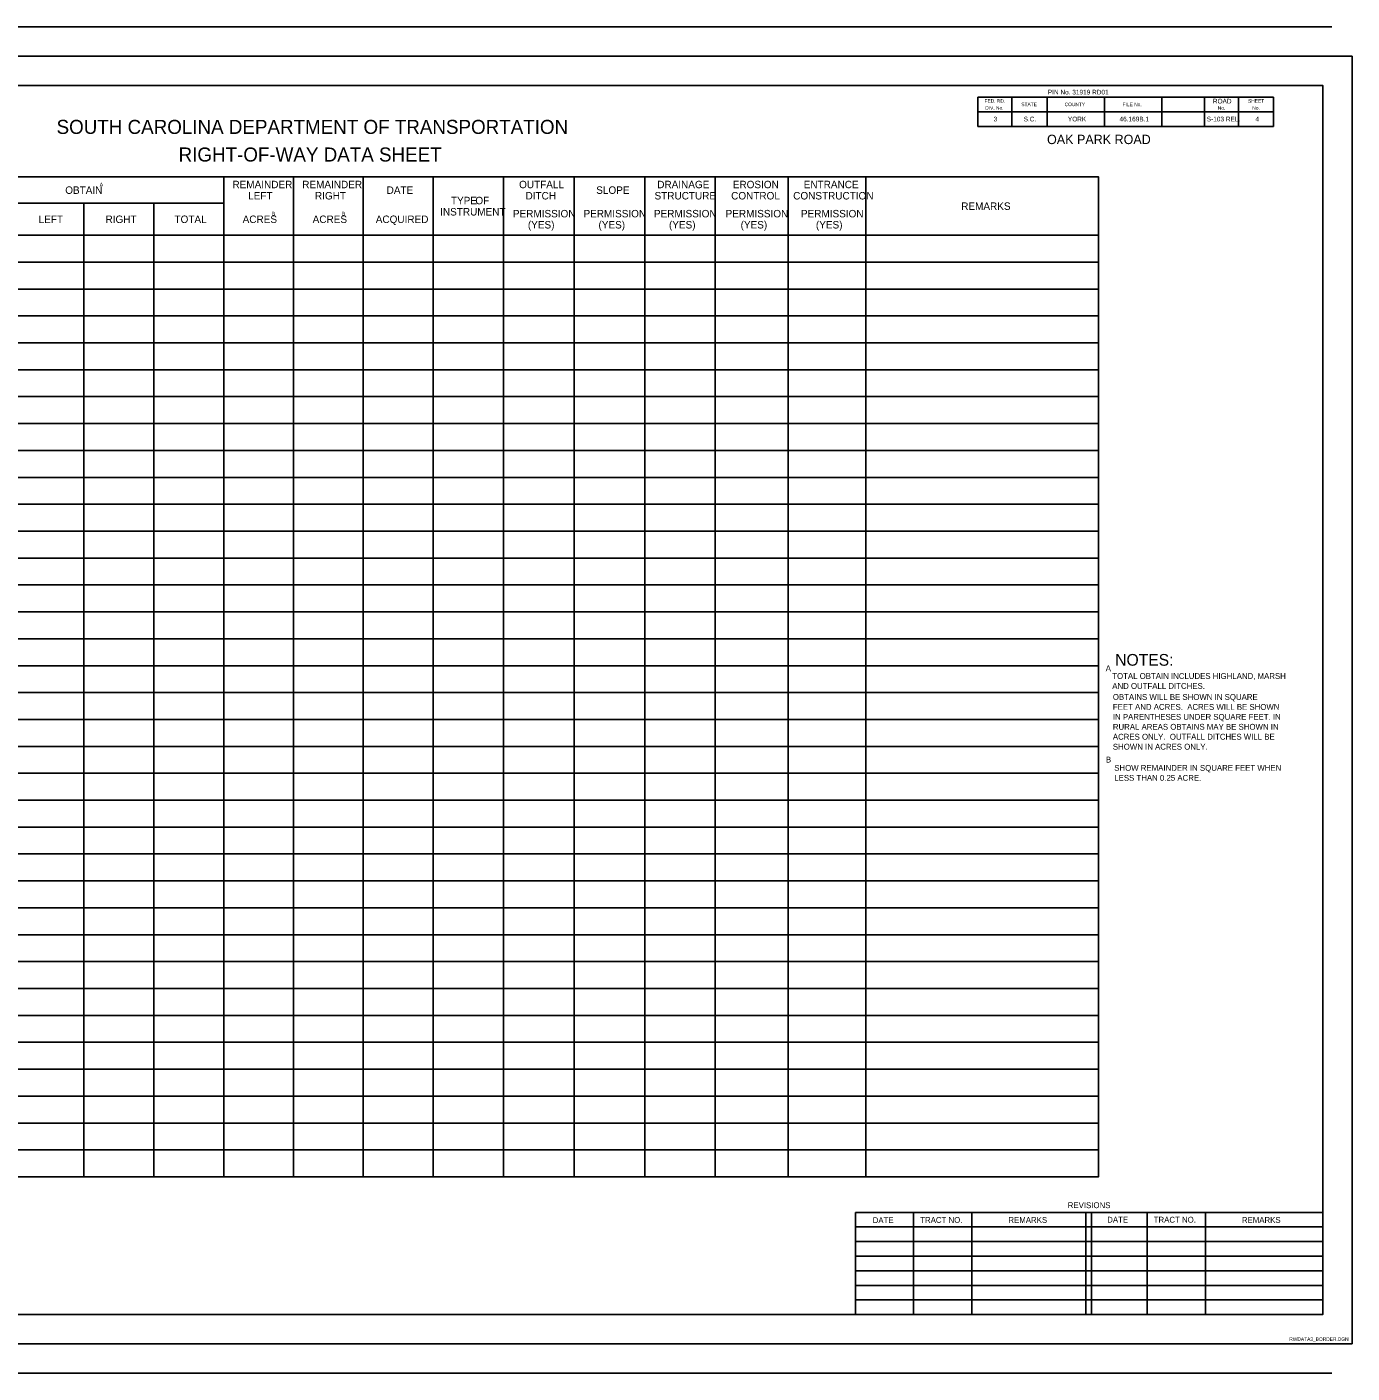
# Model space of a CAD drawing. Extents: x -19 to 1777, y -25 to 1125.
# Drawn here: x 646 to 1777, y -25 to 1125 of the extents above; entities that cross this region are included whole.
import ezdxf

# ---------------------------------------------------------------- set-up
doc = ezdxf.new("R2010")
doc.units = 0
for name, color, linetype in [('RD_SHT_Bndy', 7, 'Continuous'), ('RD_SHT_Iplotshp', 7, 'Continuous'), ('RD_SHT_MjGrid', 7, 'Continuous'), ('RD_SHT_TX', 7, 'Continuous'), ('RD_TX_RW', 7, 'Continuous')]:
    doc.layers.add(name, color=color, linetype=linetype)

msp = doc.modelspace()

# ---------------------------------------------------------------- linework, layer by layer
at = {"layer": 'RD_SHT_Bndy'}
for p, q in [((0, 1125), (1760, 1125)), ((0, 1100), (1760, 1100)), ((1457.9, 1065), (1710.4, 1065)), ((1457.9, 1065), (1457.9, 1052.5)), ((1486.9, 1065), (1486.9, 1052.5)), ((1516.9, 1065), (1516.9, 1052.5)), ((1565.9, 1065), (1565.9, 1052.5)), ((1614.9, 1065), (1614.9, 1052.5)), ((1651.4, 1065), (1651.4, 1052.5)), ((1680.4, 1065), (1680.4, 1052.5)), ((1710.4, 1065), (1710.4, 1052.5)), ((1457.9, 1052.5), (1710.4, 1052.5)), ((1457.9, 1052.5), (1457.9, 1040)), ((1486.9, 1052.5), (1486.9, 1049.4)), ((1486.9, 1049.4), (1486.9, 1040)), ((1516.9, 1052.5), (1516.9, 1040)), ((1565.9, 1052.5), (1565.9, 1040)), ((1614.9, 1052.5), (1614.9, 1040)), ((1651.4, 1052.5), (1651.4, 1040)), ((1680.4, 1052.5), (1680.4, 1040)), ((1710.4, 1052.5), (1710.4, 1040)), ((1457.9, 1040), (1710.4, 1040)), ((1353.4, 112.2), (1752.4, 112.2)), ((1353.4, 112.2), (1353.4, 25)), ((1402.9, 112.2), (1402.9, 25)), ((1452.7, 112.2), (1452.7, 25)), ((1549.9, 112.2), (1549.9, 25)), ((1554.9, 112.2), (1554.9, 25)), ((1602.3, 112.2), (1602.3, 25)), ((1652.1, 112.2), (1652.1, 25)), ((1353.4, 99.8), (1752.4, 99.8)), ((1353.4, 87.3), (1752.4, 87.3)), ((1353.4, 74.9), (1752.4, 74.9)), ((1353.4, 62.4), (1752.4, 62.4)), ((1353.4, 49.9), (1752.4, 49.9)), ((1353.4, 37.5), (1752.4, 37.5)), ((0, 0), (1760, 0)), ((0, -25), (1760, -25))]:
    msp.add_line(p, q, dxfattribs=at)
for points in [[(77.4, 1075), (1752.4, 1075), (1752.4, 25), (77.4, 25)], [(218, 142.7), (1560.9, 142.7), (1560.9, 996.8), (218, 996.8)]]:
    msp.add_lwpolyline(points, close=True, dxfattribs=at)
at = {"layer": 'RD_SHT_Iplotshp'}
msp.add_lwpolyline([(-18.6, 1100), (1777.4, 1100), (1777.4, 0), (-18.6, 0)], close=True, dxfattribs=at)
at = {"layer": 'RD_SHT_MjGrid'}
for p, q in [((218, 996.8), (1560.9, 996.8)), ((813.7, 142.7), (813.7, 996.8)), ((873.3, 142.7), (873.3, 996.8)), ((932.9, 142.7), (932.9, 996.8)), ((992.6, 142.7), (992.6, 996.8)), ((1052.8, 142.7), (1052.8, 996.8)), ((1113.1, 142.7), (1113.1, 996.8)), ((1173.3, 142.7), (1173.3, 996.8)), ((1233.6, 142.7), (1233.6, 996.8)), ((1295.7, 142.7), (1295.7, 996.8)), ((1362.1, 142.7), (1362.1, 996.8)), ((1560.9, 142.7), (1560.9, 996.8)), ((575.2, 974.4), (813.7, 974.4)), ((694.4, 142.7), (694.4, 974.4)), ((754, 142.7), (754, 974.4)), ((218, 947.1), (1560.9, 947.1)), ((992.6, 947.1), (1362.1, 947.1)), ((1362.1, 947.1), (1560.9, 947.1)), ((218, 924.1), (1560.9, 924.1)), ((218, 901.1), (1560.9, 901.1)), ((218, 878.1), (1560.9, 878.1)), ((218, 855.1), (1560.9, 855.1)), ((218, 832.1), (1560.9, 832.1)), ((218, 809.2), (1560.9, 809.2)), ((218, 786.2), (1560.9, 786.2)), ((218, 763.2), (1560.9, 763.2)), ((218, 740.2), (1560.9, 740.2)), ((218, 717.2), (1560.9, 717.2)), ((218, 694.3), (1560.9, 694.3)), ((218, 671.3), (1560.9, 671.3)), ((218, 648.3), (1560.9, 648.3)), ((218, 625.3), (1560.9, 625.3)), ((218, 602.3), (1560.9, 602.3)), ((218, 579.3), (1560.9, 579.3)), ((218, 556.4), (1560.9, 556.4)), ((218, 533.4), (1560.9, 533.4)), ((218, 510.4), (1560.9, 510.4)), ((218, 487.4), (1560.9, 487.4)), ((218, 464.4), (1560.9, 464.4)), ((218, 441.4), (1560.9, 441.4)), ((218, 418.5), (1560.9, 418.5)), ((218, 395.5), (1560.9, 395.5)), ((218, 372.5), (1560.9, 372.5)), ((218, 349.5), (1560.9, 349.5)), ((218, 326.5), (1560.9, 326.5)), ((218, 303.6), (1560.9, 303.6)), ((218, 280.6), (1560.9, 280.6)), ((218, 257.6), (1560.9, 257.6)), ((218, 234.6), (1560.9, 234.6)), ((218, 211.6), (1560.9, 211.6)), ((218, 188.6), (1560.9, 188.6)), ((218, 165.7), (1560.9, 165.7)), ((218, 142.7), (1560.9, 142.7))]:
    msp.add_line(p, q, dxfattribs=at)

# ---------------------------------------------------------------- texts
at = {"layer": 'RD_SHT_TX'}
for s, height, p in [('PIN No. 31919 RD01', 4, (1517.6, 1067.3)), ('FED. RD.', 3, (1463.5, 1060.3)), ('STATE', 3, (1494.9, 1057.3)), ('COUNTY', 3, (1531.9, 1057.3)), ('FILE No.', 3, (1581.4, 1057.3)), ('      ROAD      ', 4, (1649.3, 1059.6)), ('SHEET', 3, (1688.5, 1060.3)), ('DIV. No.', 3, (1464.1, 1054.3)), ('3', 4, (1471.2, 1044.3)), ('S.C.', 4, (1496.9, 1044.3)), ('      YORK      ', 4, (1525.5, 1044.3)), ('   46.169B.1    ', 4, (1574.2, 1044.3)), ('   S-103 REL.   ', 4, (1648.7, 1044.3)), ('No.', 3, (1662.7, 1054.3)), ('No.', 3, (1692.2, 1054.3)), ('       4        ', 4, (1684.1, 1044.3)), ('SOUTH CAROLINA DEPARTMENT OF TRANSPORTATION', 12, (671, 1033.6)), ('OAK PARK ROAD                  ', 8, (1516.9, 1024.9)), ('RIGHT-OF-WAY DATA SHEET', 12, (775.2, 1010)), ('NOTES:', 10, (1575.1, 579.3)), ('A', 5, (1567, 574.6)), ('AND OUTFALL DITCHES. ', 5, (1572.6, 559.5)), ('TOTAL OBTAIN INCLUDES HIGHLAND, MARSH', 5, (1572.6, 568)), ('OBTAINS WILL BE SHOWN IN SQUARE', 5, (1573.1, 550.1)), ('FEET AND ACRES.  ACRES WILL BE SHOWN ', 5, (1573.1, 541.6)), ('IN PARENTHESES UNDER SQUARE FEET. IN ', 5, (1573.1, 533.1)), ('RURAL AREAS OBTAINS MAY BE SHOWN IN', 5, (1573.1, 524.6)), ('ACRES ONLY.  OUTFALL DITCHES WILL BE', 5, (1573.1, 516.1)), ('SHOWN IN ACRES ONLY.', 5, (1573.1, 507.6)), ('B', 5, (1567.2, 496.6)), ('SHOW REMAINDER IN SQUARE FEET WHEN ', 5, (1574.3, 489.5)), ('LESS THAN 0.25 ACRE.', 5, (1574.3, 481)), ('REVISIONS', 5, (1534.6, 115.9)), ('DATE', 5, (1368, 103.1)), ('TRACT NO.', 5, (1408.6, 103.3)), ('REMARKS', 5, (1483.9, 103.3)), ('DATE', 5, (1568.3, 103.5)), ('TRACT NO.', 5, (1608, 103.5)), ('REMARKS', 5, (1683.3, 103.3)), ('RWDATA3_BORDER.DGN', 3, (1723.8, 2.5))]:
    msp.add_text(s, height=height, dxfattribs=at).set_placement(p)
at = {"layer": 'RD_TX_RW'}
for s, height, p in [('A', 3.19, (707.8, 988.8)), ('REMAINDER', 6.37, (821.2, 987.2)), ('REMAINDER', 6.37, (880.8, 987.2)), ('OUTFALL', 6.37, (1066, 987.2)), ('DRAINAGE', 6.37, (1184, 987.2)), ('EROSION', 6.37, (1248.5, 987.2)), ('ENTRANCE', 6.37, (1309.1, 987.2)), ('OBTAIN', 6.37, (678.4, 982.4)), ('LEFT', 6.37, (834.6, 977.6)), ('RIGHT', 6.37, (891.7, 977.6)), ('DATE', 6.37, (952.9, 982.4)), ('TYPE', 6.37, (1007.8, 973.5)), (' OF', 6.37, (1026.3, 973.5)), ('DITCH', 6.37, (1071.5, 977.6)), ('SLOPE', 6.37, (1131.9, 982.4)), ('STRUCTURE', 6.37, (1181.7, 977.6)), ('CONTROL', 6.37, (1247.1, 977.6)), ('CONSTRUCTION', 6.371, (1300.1, 977.6)), ('B', 3.19, (854.8, 963.9)), (' B', 3.19, (913.4, 963.9)), ('INSTRUMENT', 6.37, (998.6, 963.9)), ('PERMISSION', 6.37, (1060.7, 962.3)), ('PERMISSION', 6.37, (1121, 962.3)), ('PERMISSION', 6.37, (1181.2, 962.3)), ('PERMISSION', 6.37, (1242.4, 962.3)), ('PERMISSION', 6.37, (1306.7, 962.3)), ('REMARKS', 6.37, (1443.6, 968.7)), ('LEFT', 6.37, (655.7, 957.5)), ('RIGHT', 6.37, (712.8, 957.5)), ('TOTAL', 6.37, (771.7, 957.5)), ('ACRES', 6.37, (829.9, 957.5)), ('ACRES', 6.37, (889.7, 957.5)), ('ACQUIRED', 6.37, (943.6, 957.5)), ('(YES)', 6.37, (1073.5, 952.8)), ('(YES)', 6.37, (1133.8, 952.8)), ('(YES)', 6.37, (1194, 952.8)), ('(YES)', 6.37, (1255.2, 952.8)), ('(YES)', 6.37, (1319.5, 952.8))]:
    msp.add_text(s, height=height, dxfattribs=at).set_placement(p)

doc.saveas('drawing.dxf')
